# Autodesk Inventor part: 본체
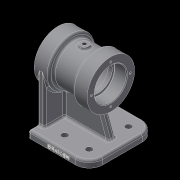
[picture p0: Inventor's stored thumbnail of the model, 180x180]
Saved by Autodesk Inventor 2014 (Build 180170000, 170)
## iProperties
Created: 2020-06
Part Number: 본체
Material: Generic
Document SubType Name: Modeling
Designer: kh
Density: 1 g/cm^3
Appearance: Default
Mass: 267.048 g
Surface Area: 643.899 cm^2
Volume: 267.048 cm^3
Author: kh
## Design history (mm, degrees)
sketch "Sketch1"
  geometry: L1 (-45, 49)-(25, 49); L2 (45, 29)-(45, -29); L3 (25, -49)-(-45, -49); L4 (-45, -49)-(-45, 49); L5 (-45, 49)-(45, -49); L6 (45, 49)-(-45, -49); A1 r 20 centre (25, 29) between (45, 29) and (25, 49); A2 r 20 centre (25, -29) between (25, -49) and (45, -29); 1 further point
  constraints: 12 end point, 4 point on circle, 4 point on line, 4 tangent, 2 centre point, 2 midpoint, 2 parallel, 1 equal radius, 1 horizontal, 1 perpendicular
  dimensions: "d0" = 90 distance of L1.start L6.start; "d1" = 98 distance of L3.end L1.start; "d2" = 20 radius of A1
extrude "Extrusion1" new body sketch "Sketch1" distance "d3" = 10; taper "d4" = 0 deg
workplane "Work Plane1"
sketch "Sketch7"
  geometry: L1 (-25, 10)-(45, 10) reference; L2 (-25, 10)-(-45, 10) reference; L3 (-45, 0)-(-45, 10) reference; L4 (45, 0)-(45, 10) reference; L5 (45, 0)-(-25, 0) reference; L6 (-45, 0)-(-25, 0) reference; L7 (50, 115)-(28, 115); L8 (28, 115)-(28, 109); L9 (28, 109)-(-6, 109); L10 (-6, 109)-(-6, 115); L11 (-6, 115)-(-28, 115); L12 (-28, 115)-(-28, 80); L13 (-28, 80)-(50, 80); L14 (50, 80)-(50, 115); 1 further point
  constraints: 16 end point, 6 parallel, 1 collinear, 1 perpendicular
  dimensions: "d28" = 80 distance between parallel lines of L5 L13; "d29" = 5 distance between parallel lines of L4 L14; "d30" = 70 diameter of L7 L13; "d31" = 58 diameter of L9 L13; "d32" = 70 diameter of L11 L13; "d33" = 22 distance of L7.start L7.end; "d34" = 22 distance of L10.end L11.end; "d35" = 78 distance between parallel lines of L12 L14
revolve "Revolution1" sketch "Sketch7" stored, may be unused: angle "d36" = 90 deg
sketch "Sketch8"
  geometry: L1 (10, 98)-(10, 0) reference; L2 (80, 84)-(10, 84); L3 (80, 14)-(10, 14); L4 (10, 84)-(10, 14); A1 r 35 centre (80, 49) between (80, 14) and (80, 84) reference; 1 further point
  constraints: 6 end point, 2 point on circle, 2 point on line, 2 tangent, 1 collinear
  dimensions: "d37" = 35 vertical distance of point (0, 49) L2.end; "d38" = 35 vertical distance of L3.end point (0, 49)
extrude "Extrusion5" join sketch "Sketch8" distance "d39" = 10; taper "d40" = 0 deg
sketch "Sketch9"
  geometry: L1 (-6, 51)-(28, 51) reference; L2 (-28, 45)-(-6, 45) reference; L3 (-6, 45)-(-6, 115) reference; L4 (-28, 45)-(-28, 115) reference; L5 (-25, 10)-(45, 10) reference; L6 (-25, 10)-(-45, 10) reference; L7 (-17.261, 45)-(-30, 10); 1 further point
  constraints: 2 end point, 2 point on line
  dimensions: "d41" = 15 distance of L6.end L7.end; "d42" = 70 deg angle of L5 L7
feature "Rib2" sketch "Sketch9" dims "d43" = 1, "d44" = 10, "d45" = 0, "d46" = 0, "d47" = 1, "d48" = 1
sketch "Sketch10"
  geometry: L1 (50, 45)-(50, 115) reference; L2 (28, 115)-(50, 115) reference; L3 (-6, 109)-(28, 109) reference; L4 (-28, 115)-(-6, 115) reference; L5 (-28, 45)-(-28, 115) reference; L6 (-28, 45)-(-17.261, 45) reference; L7 (45, 45)-(50, 45) reference; L8 (50, 80)-(-28, 80); L9 (50, 103.5)-(32.3, 103.5); L10 (32, 103.2)-(32, 100); L11 (32, 100)-(26, 100); L12 (26, 100)-(26, 103); L13 (26, 103)-(-4, 103); L14 (-4, 103)-(-4, 100); L15 (-4, 100)-(-10, 100); L16 (-10, 100)-(-10, 103.2); L17 (-10.3, 103.5)-(-28, 103.5); A1 r 0.3 centre (32.3, 103.2) between (32.3, 103.5) and (32, 103.2); A2 r 0.3 centre (-10.3, 103.2) between (-10, 103.2) and (-10.3, 103.5); 3 further points
  constraints: 20 end point, 7 parallel, 6 point on line, 4 point on circle, 4 tangent, 2 centre point, 2 midpoint, 2 perpendicular, 1 equal radius
  dimensions: "d49" = 47 diameter of L9 L8; "d50" = 40 diameter of L11 L8; "d51" = 46 diameter of L13 L8; "d52" = 40 diameter of L15 L8; "d53" = 47 diameter of L17 L8; "d54" = 18 distance of L9.start point (32, 103.5); "d55" = 18 distance of point (-10, 103.5) L17.end; "d56" = 30 distance of L12.end L13.end; "d57" = 6 distance of L14.end L15.end; "d58" = 0.3 radius of A1
revolve "Revolution2" sketch "Sketch10" stored, may be unused: angle "d59" = 90 deg
sketch "Sketch12"
  geometry: C1 r 23.5 at (0, 0) reference; 2 further points
  constraints: 1 horizontal alignment
  dimensions: "d75" = 28.5 distance of C1.centre point (-28.5, 0)
hole "Hole2" sketch "Sketch12" at (-28.5, 0) diameter "d76" = 3.242; stored, may be unused: countersink angle "d80" = 90 deg, drill point angle "d82" = 118 deg; dims "d77" = 10, "d78" = 4, "d79" = 2, "d81" = 12
pattern_circular "Circular Pattern1" dims angle "d84" = 360 deg
workplane "Work Plane3"
mirror "Mirror1"
sketch "Sketch13"
  geometry: A1 r 20 centre (25, -29) between (25, -49) and (45, -29) reference; 2 further points
  constraints: 1 coincident
hole "Hole3" sketch "Sketch13" at (25, -29) diameter "d87" = 9; stored, may be unused: countersink angle "d91" = 90 deg, drill point angle "d93" = 118 deg; dims "d88" = 10, "d89" = 4, "d90" = 2, "d92" = 12
pattern_linear "Rectangular Pattern1" dims "d96" = 36, "d99" = 58
fillet "Fillet1" dims "d100" = 3
fillet "Fillet2" dims "d101" = 3
fillet "Fillet3" dims "d102" = 3
chamfer "Chamfer1" distance "d103" = 1; stored, may be unused: second distance "d104" = 2, angle "d105" = 45 deg
sketch "Sketch14"
  geometry: L1 (67, 0)-(0, 0) reference; L2 (-3, 7)-(-3, 0) reference; 2 further points
  constraints: 1 other
  dimensions: "d106" = 45 distance from line of point (42, 4) L2; "d107" = 4 distance from line of L1 point (42, 4)
emboss "Emboss1" sketch "Sketch14" dims "d0" = 90, "d1" = 98, "d2" = 20, "d108" = 0.5, "d109" = 0
workplane "Work Plane4"
sketch "Sketch15"
  geometry: L1 (-50, 24.5)-(-50, -24.5) reference; L2 (3, 29)-(-25, 29) reference; C1 r 6 at (-11, 0); 3 further points
  constraints: 2 horizontal alignment, 2 midpoint, 1 centre point, 1 vertical alignment
  dimensions: "d111" = 12 diameter of C1
extrude "Extrusion7" join sketch "Sketch15" stored distance "d112" = 3; taper "d113" = 0 deg
hole "Hole4" diameter "d116" = 5.188; stored, may be unused: countersink angle "d120" = 90 deg, drill point angle "d122" = 118 deg; dims "d114" = 10, "d115" = 10, "d117" = 10, "d118" = 4, "d119" = 2, "d121" = 16.5
fillet "Fillet4" dims "d123" = 3
body "Solid1"
node "Projected Loop3"
other parameters: "d9" = 5, "d110" = 112
